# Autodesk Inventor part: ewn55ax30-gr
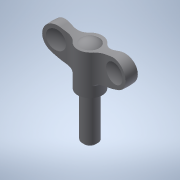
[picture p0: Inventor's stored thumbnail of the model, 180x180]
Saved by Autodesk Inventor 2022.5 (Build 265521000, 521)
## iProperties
Created: 2016-12
Part Number: ewn55ax30-gr
Material: 一般
Document SubType Name: Modeling
Designer: imaocorp
Density: 1 g/cm^3
Appearance: 既定
Author: imaocorp
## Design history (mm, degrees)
node "ewn55ax30-gr.x_t1"
node "ewn55ax30-gr"
node "Base1"
